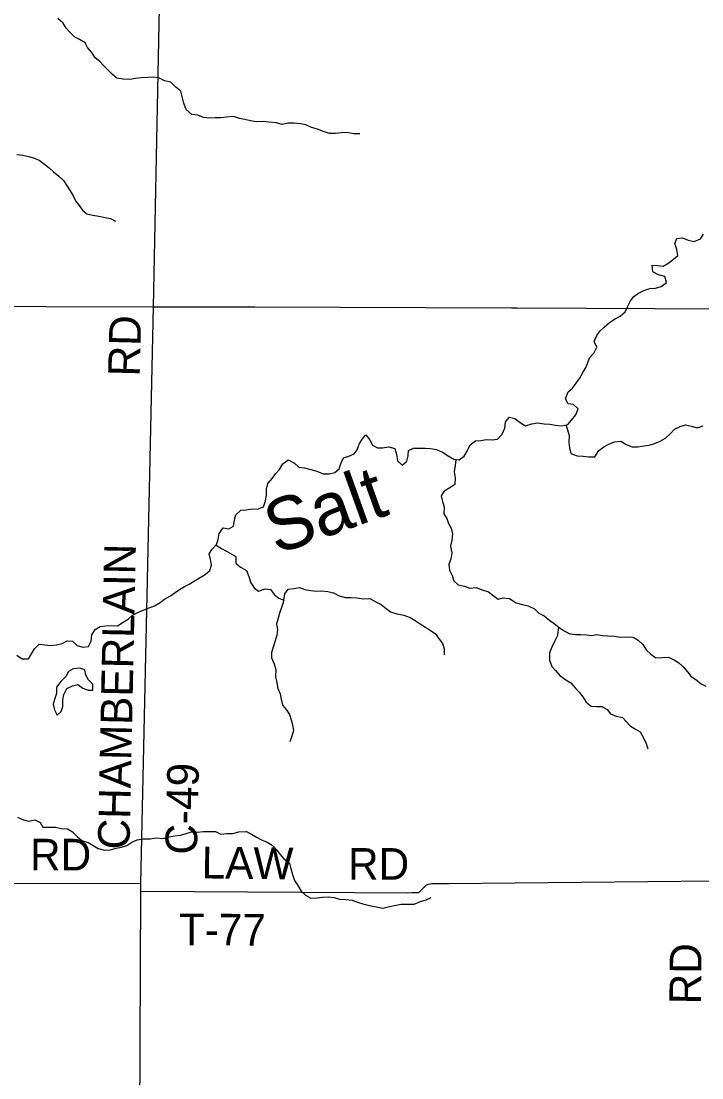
# Model space of a CAD drawing. Extents: x 1857828 to 2277390, y 930619 to 1324581.
# Drawn here: x 2087718 to 2094171, y 1172535 to 1182554 of the extents above; entities that cross this region are included whole.
import ezdxf

# ---------------------------------------------------------------- set-up
doc = ezdxf.new("R2010")
doc.units = 0
for name, color, linetype in [('GM_X_County_Road', 7, 'Continuous'), ('GM_X_County_Road_Text', 7, 'Continuous'), ('GM_X_Minor_Lake', 7, 'Continuous'), ('GM_X_Minor_River', 7, 'Continuous'), ('GM_X_Minor_River_Text', 7, 'Continuous'), ('GM_X_State_Route', 7, 'Continuous'), ('GM_X_Township_Road', 7, 'Continuous'), ('GM_X_Township_Road_Text', 7, 'Continuous'), ('GM_X_Township_ROW', 7, 'Continuous')]:
    doc.layers.add(name, color=color, linetype=linetype)

msp = doc.modelspace()

# ---------------------------------------------------------------- linework, layer by layer
at = {"layer": 'GM_X_County_Road'}
for points in [[(2088974, 1179845), (2089067, 1184581), (2089106, 1185944), (2089111, 1186163), (2089116, 1186313), (2089121, 1186458), (2089122, 1186562), (2089134, 1186691), (2089145, 1186783), (2089174, 1186946), (2089241, 1187221), (2089274, 1187342), (2089316, 1187466), (2089371, 1187611), (2089403, 1187692), (2089420, 1187738), (2089454, 1187798), (2089496, 1187877), (2089744, 1188264), (2090066, 1188771), (2090290, 1189083), (2090301, 1189100)], [(2088854, 1174305), (2088854, 1174379), (2088974, 1179845)]]:
    msp.add_lwpolyline(points, dxfattribs=at)
at = {"layer": 'GM_X_Minor_Lake'}
for points in [[(2088397, 1176211), (2088398, 1176267), (2088357, 1176309), (2088331, 1176354), (2088322, 1176404), (2088271, 1176420), (2088213, 1176413), (2088167, 1176389), (2088142, 1176341), (2088094, 1176293), (2088055, 1176240), (2088053, 1176178), (2088039, 1176130), (2088023, 1176078), (2088035, 1176024), (2088061, 1175973), (2088099, 1176007)], [(2088099, 1176007), (2088115, 1176055), (2088115, 1176118), (2088122, 1176168), (2088152, 1176226), (2088204, 1176250), (2088257, 1176264), (2088303, 1176231), (2088355, 1176209), (2088397, 1176211)]]:
    msp.add_lwpolyline(points, dxfattribs=at)
at = {"layer": 'GM_X_Minor_River'}
for points in [[(2090929, 1181486), (2090869, 1181486), (2090808, 1181497), (2090756, 1181495), (2090698, 1181489), (2090641, 1181489), (2090585, 1181506), (2090527, 1181530), (2090472, 1181544), (2090418, 1181569), (2090366, 1181581), (2090306, 1181585), (2090247, 1181586), (2090193, 1181572), (2090139, 1181588), (2090066, 1181596), (2090012, 1181601), (2089947, 1181599), (2089893, 1181609), (2089839, 1181620), (2089789, 1181632), (2089730, 1181648), (2089666, 1181644), (2089612, 1181637), (2089559, 1181637), (2089503, 1181635), (2089447, 1181639), (2089394, 1181662), (2089336, 1181668), (2089284, 1181717), (2089262, 1181775), (2089248, 1181827), (2089232, 1181890), (2089186, 1181928), (2089138, 1181974), (2089077, 1181989), (2089025, 1182017), (2088965, 1182023), (2088915, 1182020), (2088856, 1182016), (2088802, 1182010), (2088748, 1182000), (2088685, 1182003), (2088625, 1182013), (2088585, 1182047), (2088539, 1182092), (2088503, 1182130), (2088464, 1182172), (2088420, 1182205), (2088390, 1182257), (2088348, 1182303), (2088324, 1182348), (2088272, 1182378), (2088226, 1182400), (2088182, 1182445), (2088145, 1182487), (2088117, 1182534), (2088067, 1182580)], [(2087677, 1181290), (2087735, 1181283), (2087792, 1181271), (2087842, 1181253), (2087890, 1181235), (2087940, 1181198), (2087986, 1181160), (2088025, 1181125), (2088075, 1181083), (2088121, 1181043), (2088149, 1180998), (2088183, 1180946), (2088211, 1180896), (2088233, 1180849), (2088267, 1180807), (2088301, 1180762), (2088341, 1180728), (2088399, 1180714), (2088456, 1180704), (2088514, 1180691), (2088564, 1180681), (2088613, 1180657)], [(2090825, 1178430), (2090875, 1178450), (2090905, 1178490), (2090924, 1178542), (2090952, 1178590), (2090986, 1178630), (2091022, 1178588), (2091048, 1178534), (2091095, 1178509), (2091145, 1178509), (2091205, 1178517), (2091260, 1178503), (2091275, 1178448), (2091287, 1178386), (2091329, 1178344), (2091374, 1178382), (2091388, 1178432), (2091390, 1178482), (2091439, 1178504), (2091495, 1178504), (2091549, 1178505), (2091600, 1178501), (2091656, 1178491), (2091712, 1178468), (2091766, 1178432), (2091821, 1178402), (2091871, 1178395), (2091917, 1178429), (2091950, 1178483), (2091974, 1178536), (2092024, 1178574), (2092075, 1178579), (2092127, 1178587), (2092183, 1178583), (2092234, 1178591), (2092278, 1178637), (2092302, 1178695), (2092309, 1178753), (2092347, 1178799), (2092397, 1178787), (2092449, 1178748), (2092500, 1178716), (2092560, 1178736), (2092614, 1178744), (2092675, 1178737), (2092731, 1178731), (2092785, 1178723), (2092844, 1178717), (2092900, 1178730), (2092934, 1178770), (2092975, 1178822), (2092999, 1178877), (2092953, 1178919), (2092903, 1178925), (2092879, 1178974), (2092905, 1179038), (2092945, 1179074), (2092980, 1179120), (2093010, 1179166), (2093040, 1179216), (2093067, 1179262), (2093087, 1179308), (2093105, 1179360), (2093146, 1179406), (2093174, 1179463), (2093150, 1179515), (2093174, 1179573), (2093205, 1179613), (2093245, 1179653), (2093295, 1179695), (2093342, 1179727), (2093398, 1179757), (2093445, 1179797), (2093465, 1179845), (2093493, 1179901), (2093526, 1179943), (2093570, 1179975), (2093622, 1179999), (2093677, 1180019), (2093731, 1180023), (2093785, 1180038), (2093836, 1180074), (2093820, 1180133), (2093760, 1180149), (2093707, 1180177), (2093701, 1180240), (2093754, 1180236), (2093804, 1180229), (2093858, 1180263), (2093903, 1180297), (2093943, 1180331), (2093935, 1180389), (2093915, 1180444), (2093934, 1180494), (2093988, 1180498), (2094040, 1180477), (2094099, 1180465), (2094157, 1180489), (2094185, 1180535)], [(2092883, 1178726), (2092898, 1178678), (2092912, 1178624), (2092910, 1178559), (2092915, 1178509), (2092929, 1178453), (2092988, 1178431), (2093046, 1178430), (2093100, 1178422), (2093157, 1178422), (2093193, 1178482), (2093241, 1178516), (2093290, 1178542), (2093344, 1178566), (2093402, 1178571), (2093453, 1178541), (2093509, 1178519), (2093563, 1178518), (2093622, 1178526), (2093672, 1178532), (2093722, 1178550), (2093775, 1178570), (2093825, 1178600), (2093871, 1178640), (2093912, 1178686), (2093964, 1178711), (2094015, 1178725), (2094073, 1178715), (2094125, 1178697), (2094184, 1178716)], [(2087676, 1176542), (2087728, 1176509), (2087789, 1176509), (2087817, 1176555), (2087845, 1176603), (2087888, 1176647), (2087944, 1176639), (2088000, 1176635), (2088053, 1176640), (2088107, 1176654), (2088155, 1176678), (2088206, 1176676), (2088248, 1176635), (2088304, 1176619), (2088358, 1176625), (2088383, 1176675), (2088387, 1176735), (2088419, 1176787), (2088466, 1176815), (2088518, 1176821), (2088576, 1176825), (2088631, 1176819), (2088685, 1176855), (2088734, 1176884), (2088774, 1176920), (2088824, 1176948), (2088875, 1176970), (2088933, 1176992), (2088981, 1177010), (2089036, 1177042), (2089076, 1177074), (2089135, 1177106), (2089177, 1177136), (2089219, 1177164), (2089268, 1177193), (2089316, 1177219), (2089368, 1177249), (2089415, 1177279), (2089463, 1177307), (2089506, 1177345), (2089524, 1177397), (2089514, 1177448), (2089502, 1177504), (2089528, 1177548), (2089571, 1177590), (2089585, 1177638), (2089597, 1177696), (2089632, 1177750), (2089686, 1177740), (2089732, 1177766), (2089740, 1177824), (2089755, 1177872), (2089801, 1177916), (2089851, 1177920), (2089908, 1177930), (2089960, 1177928), (2090016, 1177948), (2090035, 1178006), (2090043, 1178058), (2090045, 1178116), (2090057, 1178170), (2090100, 1178219), (2090130, 1178263), (2090166, 1178303), (2090199, 1178357), (2090249, 1178393), (2090309, 1178362), (2090350, 1178324), (2090404, 1178318), (2090464, 1178303), (2090520, 1178287), (2090581, 1178263), (2090639, 1178260), (2090693, 1178274), (2090732, 1178310), (2090752, 1178366), (2090774, 1178414), (2090825, 1178430)], [(2091838, 1178399), (2091832, 1178341), (2091822, 1178281), (2091832, 1178223), (2091830, 1178160), (2091781, 1178129), (2091729, 1178097), (2091701, 1178053), (2091711, 1178000), (2091729, 1177946), (2091724, 1177882), (2091752, 1177839), (2091770, 1177791), (2091796, 1177747), (2091808, 1177692), (2091802, 1177632), (2091788, 1177576), (2091800, 1177512), (2091791, 1177457), (2091773, 1177401), (2091779, 1177349), (2091805, 1177297), (2091821, 1177246), (2091861, 1177210), (2091921, 1177196), (2091972, 1177179), (2092032, 1177185), (2092088, 1177163), (2092149, 1177144), (2092189, 1177110), (2092239, 1177074), (2092289, 1177085), (2092348, 1177081), (2092412, 1177039), (2092470, 1177024), (2092526, 1177010), (2092583, 1176982), (2092627, 1176941), (2092675, 1176915), (2092729, 1176872), (2092771, 1176842), (2092817, 1176806), (2092860, 1176777), (2092914, 1176749), (2092970, 1176739), (2093025, 1176738), (2093075, 1176734), (2093127, 1176728), (2093177, 1176738), (2093228, 1176730), (2093280, 1176725), (2093342, 1176721), (2093401, 1176713), (2093463, 1176716), (2093521, 1176714), (2093568, 1176686), (2093612, 1176645), (2093646, 1176589), (2093686, 1176551), (2093736, 1176518), (2093794, 1176520), (2093853, 1176522), (2093909, 1176499), (2093953, 1176471), (2093995, 1176431), (2094035, 1176384), (2094065, 1176342), (2094116, 1176308), (2094164, 1176271), (2094208, 1176247)], [(2089566, 1177585), (2089617, 1177554), (2089665, 1177527), (2089709, 1177503), (2089755, 1177477), (2089753, 1177416), (2089797, 1177376), (2089856, 1177346), (2089876, 1177287), (2089897, 1177227), (2089928, 1177180), (2089968, 1177148), (2090030, 1177170), (2090082, 1177166), (2090120, 1177115), (2090161, 1177083), (2090209, 1177063), (2090193, 1177014), (2090168, 1176942), (2090154, 1176892), (2090138, 1176838), (2090150, 1176784), (2090141, 1176733), (2090127, 1176679), (2090109, 1176627), (2090093, 1176567), (2090092, 1176517), (2090116, 1176460), (2090134, 1176404), (2090128, 1176340), (2090142, 1176281), (2090152, 1176225), (2090174, 1176175), (2090182, 1176122), (2090198, 1176066), (2090230, 1176026), (2090262, 1175981), (2090278, 1175929), (2090292, 1175881), (2090299, 1175828), (2090285, 1175774), (2090265, 1175720)], [(2090208, 1177063), (2090219, 1177125), (2090249, 1177169), (2090302, 1177173), (2090358, 1177185), (2090408, 1177166), (2090463, 1177154), (2090515, 1177148), (2090567, 1177153), (2090626, 1177147), (2090680, 1177133), (2090734, 1177106), (2090792, 1177088), (2090843, 1177088), (2090901, 1177086), (2090963, 1177077), (2091024, 1177081), (2091080, 1177047), (2091130, 1177022), (2091178, 1176984), (2091218, 1176954), (2091281, 1176935), (2091347, 1176921), (2091405, 1176898), (2091452, 1176870), (2091502, 1176840), (2091550, 1176807), (2091598, 1176775), (2091642, 1176747), (2091674, 1176702), (2091712, 1176652), (2091728, 1176604), (2091728, 1176545)], [(2092811, 1176811), (2092803, 1176729), (2092775, 1176673), (2092749, 1176619), (2092728, 1176563), (2092726, 1176495), (2092750, 1176436), (2092784, 1176398), (2092824, 1176350), (2092880, 1176309), (2092929, 1176281), (2092971, 1176234), (2093007, 1176192), (2093043, 1176146), (2093073, 1176097), (2093121, 1176059), (2093173, 1176055), (2093224, 1176056), (2093272, 1176026), (2093304, 1175986), (2093358, 1175965), (2093418, 1175951), (2093454, 1175913), (2093491, 1175872), (2093541, 1175840), (2093585, 1175814), (2093617, 1175759), (2093643, 1175705), (2093659, 1175655)], [(2087683, 1175006), (2087742, 1174982), (2087792, 1174970), (2087848, 1174980), (2087899, 1174957), (2087923, 1174911), (2087987, 1174913), (2088043, 1174912), (2088098, 1174900), (2088158, 1174896), (2088204, 1174867), (2088254, 1174821), (2088294, 1174785), (2088353, 1174766), (2088401, 1174738), (2088449, 1174708), (2088509, 1174693), (2088566, 1174697), (2088618, 1174713), (2088670, 1174723), (2088721, 1174739), (2088769, 1174768), (2088819, 1174792), (2088874, 1174802), (2088942, 1174802), (2089001, 1174812), (2089063, 1174803), (2089121, 1174821), (2089174, 1174829), (2089230, 1174837), (2089284, 1174851), (2089333, 1174866), (2089391, 1174864)], [(2089391, 1174864), (2089445, 1174870), (2089502, 1174872), (2089560, 1174869), (2089612, 1174845), (2089667, 1174851), (2089725, 1174853), (2089783, 1174866), (2089856, 1174870), (2089902, 1174846), (2089948, 1174817), (2089996, 1174793), (2090049, 1174769), (2090097, 1174742), (2090139, 1174696), (2090175, 1174654), (2090209, 1174611), (2090263, 1174571), (2090275, 1174521), (2090291, 1174464), (2090311, 1174406), (2090341, 1174357), (2090373, 1174305), (2090413, 1174267), (2090464, 1174240), (2090524, 1174242), (2090576, 1174248), (2090631, 1174250), (2090685, 1174245), (2090735, 1174229), (2090795, 1174227), (2090856, 1174219), (2090908, 1174200), (2090956, 1174184), (2091019, 1174170), (2091083, 1174155), (2091147, 1174145), (2091198, 1174155), (2091256, 1174169), (2091320, 1174180), (2091381, 1174182), (2091445, 1174182), (2091504, 1174206), (2091558, 1174223), (2091604, 1174245)]]:
    msp.add_lwpolyline(points, dxfattribs=at)
at = {"layer": 'GM_X_State_Route'}
for points in [[(2085062, 1179640), (2085250, 1179662), (2085997, 1179782), (2086116, 1179799), (2086274, 1179816), (2086429, 1179830), (2086595, 1179840), (2086762, 1179848), (2086929, 1179851), (2088974, 1179845)], [(2088974, 1179845), (2089935, 1179845), (2092367, 1179834), (2092420, 1179834)], [(2092420, 1179834), (2094381, 1179825), (2098450, 1179801), (2098487, 1179800)]]:
    msp.add_lwpolyline(points, dxfattribs=at)
at = {"layer": 'GM_X_Township_Road'}
for points in [[(2086280, 1174396), (2086327, 1174395), (2086437, 1174391), (2087247, 1174381), (2088854, 1174379)], [(2088841, 1171400), (2088854, 1174305)], [(2088854, 1174305), (2091384, 1174290), (2091422, 1174291), (2091443, 1174291), (2091454, 1174291), (2091457, 1174292)]]:
    msp.add_lwpolyline(points, dxfattribs=at)
at = {"layer": 'GM_X_Township_ROW'}
msp.add_lwpolyline([(2091457, 1174292), (2091464, 1174293), (2091488, 1174293), (2091511, 1174313), (2091533, 1174337), (2091547, 1174351), (2091557, 1174361), (2091579, 1174370), (2091611, 1174376), (2091660, 1174376), (2091774, 1174377), (2094289, 1174402)], dxfattribs=at)

# ---------------------------------------------------------------- texts
at = {"layer": 'GM_X_County_Road_Text'}
for s, rotation, p in [('RD', 88.5174, (2088842, 1179182)), ('CHAMBERLAIN', 88.7811, (2088745, 1174698)), ('C-49', 88.6273, (2089384, 1174648)), ('RD', 89.5045, (2094163, 1173231))]:
    msp.add_text(s, height=300, rotation=rotation, dxfattribs=at).set_placement(p)
at = {"layer": 'GM_X_Minor_River_Text'}
msp.add_text('Salt', height=500.2, rotation=19.6795, dxfattribs=at).set_placement((2090138, 1177492))
at = {"layer": 'GM_X_Township_Road_Text'}
for s, rotation, p in [('RD', 0, (2087803, 1174501)), ('LAW', 359.3972, (2089428, 1174426)), ('RD', 0, (2090817, 1174413)), ('T-77', 359.6465, (2089212, 1173793))]:
    msp.add_text(s, height=300, rotation=rotation, dxfattribs=at).set_placement(p)

doc.saveas('drawing.dxf')
